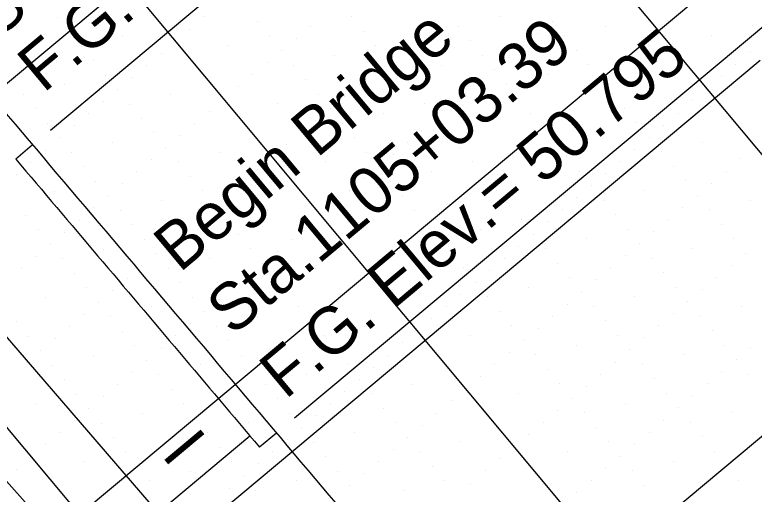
# Model space of a CAD drawing. Extents: x 2042995 to 2043795, y 305365 to 306249.
# Drawn here: x 2043257.9 to 2043297.1, y 305860.14 to 305885.54 of the extents above; entities that cross this region are included whole.
import ezdxf

# ---------------------------------------------------------------- set-up
doc = ezdxf.new("R2010")
doc.units = 0
for name, color, linetype in [('BR_AUTO DIMENSION', 7, 'Continuous'), ('BR_CENTER LINES', 7, 'Continuous'), ('BR_CONCRETE', 7, 'Continuous'), ('BR_EXIST_GROUND_CL', 7, 'Continuous'), ('BR_EXIST_GROUND_LT', 7, 'Continuous'), ('BR_GRID DOTS', 7, 'Continuous'), ('BR_GRID LINES', 7, 'Continuous'), ('BR_TEXT', 7, 'Continuous')]:
    doc.layers.add(name, color=color, linetype=linetype)

msp = doc.modelspace()

# ---------------------------------------------------------------- linework, layer by layer
at = {"layer": 'BR_AUTO DIMENSION'}
for p, q in [((2043259.789, 305879.429), (2043308.056, 305919.741)), ((2043272.73, 305864.18), (2043320.876, 305904.391))]:
    msp.add_line(p, q, dxfattribs=at)
at = {"layer": 'BR_CENTER LINES'}
msp.add_line((2043297.418, 305883.113), (2043258.691, 305850.769), dxfattribs=at)
at = {"layer": 'BR_CONCRETE'}
for p, q in [((2043258.829, 305878.628), (2043257.952, 305877.895)), ((2043271.771, 305863.378), (2043270.876, 305862.631)), ((2043270.361, 305863.212), (2043263.229, 305857.255))]:
    msp.add_line(p, q, dxfattribs=at)
for points in [[(2043139.109, 306017.548), (2043148.199, 306007.16), (2043160.233, 305993.368), (2043172.245, 305979.557), (2043184.234, 305965.727), (2043196.201, 305951.879), (2043208.145, 305938.012), (2043220.067, 305924.126), (2043231.966, 305910.221), (2043243.843, 305896.297), (2043255.698, 305882.355), (2043267.529, 305868.394), (2043279.339, 305854.414), (2043291.126, 305840.415), (2043302.89, 305826.398), (2043314.632, 305812.361), (2043326.352, 305798.306), (2043338.049, 305784.233), (2043349.724, 305770.14), (2043361.376, 305756.029), (2043373.005, 305741.899), (2043384.613, 305727.75), (2043396.197, 305713.582), (2043407.76, 305699.396), (2043419.299, 305685.191), (2043430.817, 305670.967), (2043442.311, 305656.724), (2043453.784, 305642.463), (2043465.234, 305628.182), (2043476.661, 305613.883), (2043488.066, 305599.566), (2043499.448, 305585.229), (2043510.808, 305570.874), (2043522.146, 305556.5), (2043533.461, 305542.107), (2043544.753, 305527.695), (2043547.219, 305524.543)], [(2043257.952, 305877.895), (2043266.634, 305867.646), (2043270.876, 305862.631)]]:
    msp.add_spline(points, degree=3, dxfattribs=at)
at = {"layer": 'BR_EXIST_GROUND_CL'}
msp.add_lwpolyline([(2043190.108, 305945.543), (2043206.09, 305927.482), (2043206.623, 305926.882), (2043222.659, 305908.759), (2043222.667, 305908.751), (2043222.878, 305908.512), (2043223.372, 305907.946), (2043239.214, 305889.588), (2043239.703, 305889.028), (2043255.551, 305870.664), (2043255.733, 305870.455), (2043271.607, 305852.06)], dxfattribs=at)
at = {"layer": 'BR_EXIST_GROUND_LT'}
msp.add_lwpolyline([(2043232.345, 305892.17), (2043232.671, 305891.863), (2043234.146, 305890.054), (2043243.505, 305878.139), (2043246.167, 305875.173), (2043248.035, 305872.016), (2043253.891, 305864.802), (2043257.466, 305860.822), (2043270.561, 305846.11), (2043270.909, 305845.721)], dxfattribs=at)
at = {"layer": 'BR_GRID DOTS'}
for p, q in [((2043260.145, 305885.418), (2043260.145, 305885.418)), ((2043267.956, 305885.426), (2043267.956, 305885.426)), ((2043275.766, 305885.435), (2043275.766, 305885.435)), ((2043283.576, 305885.443), (2043283.576, 305885.443)), ((2043257.969, 305884.903), (2043257.969, 305884.903)), ((2043270.773, 305885.173), (2043270.773, 305885.173)), ((2043273.59, 305884.92), (2043273.59, 305884.92)), ((2043279.991, 305885.055), (2043279.991, 305885.055)), ((2043281.4, 305884.929), (2043281.4, 305884.929)), ((2043286.393, 305885.19), (2043286.393, 305885.19)), ((2043289.21, 305884.937), (2043289.21, 305884.937)), ((2043297.02, 305884.946), (2043297.02, 305884.946)), ((2043267.188, 305884.785), (2043267.188, 305884.785)), ((2043276.407, 305884.667), (2043276.407, 305884.667)), ((2043285.626, 305884.549), (2043285.626, 305884.549)), ((2043263.603, 305884.397), (2043263.603, 305884.397)), ((2043266.42, 305884.144), (2043266.42, 305884.144)), ((2043271.414, 305884.406), (2043271.414, 305884.406)), ((2043272.822, 305884.279), (2043272.822, 305884.279)), ((2043279.224, 305884.414), (2043279.224, 305884.414)), ((2043282.041, 305884.161), (2043282.041, 305884.161)), ((2043287.034, 305884.423), (2043287.034, 305884.423)), ((2043294.844, 305884.432), (2043294.844, 305884.432)), ((2043261.427, 305883.883), (2043261.427, 305883.883)), ((2043269.238, 305883.891), (2043269.238, 305883.891)), ((2043277.048, 305883.9), (2043277.048, 305883.9)), ((2043278.456, 305883.773), (2043278.456, 305883.773)), ((2043284.858, 305883.908), (2043284.858, 305883.908)), ((2043265.653, 305883.503), (2043265.653, 305883.503)), ((2043272.055, 305883.638), (2043272.055, 305883.638)), ((2043274.872, 305883.385), (2043274.872, 305883.385)), ((2043282.682, 305883.394), (2043282.682, 305883.394)), ((2043287.675, 305883.655), (2043287.675, 305883.655)), ((2043296.894, 305883.537), (2043296.894, 305883.537)), ((2043262.068, 305883.115), (2043262.068, 305883.115)), ((2043271.287, 305882.997), (2043271.287, 305882.997)), ((2043277.689, 305883.132), (2043277.689, 305883.132)), ((2043284.091, 305883.267), (2043284.091, 305883.267)), ((2043264.885, 305882.862), (2043264.885, 305882.862)), ((2043272.696, 305882.871), (2043272.696, 305882.871)), ((2043280.506, 305882.879), (2043280.506, 305882.879)), ((2043283.323, 305882.626), (2043283.323, 305882.626)), ((2043288.316, 305882.888), (2043288.316, 305882.888)), ((2043296.126, 305882.896), (2043296.126, 305882.896)), ((2043262.709, 305882.348), (2043262.709, 305882.348)), ((2043264.118, 305882.221), (2043264.118, 305882.221)), ((2043270.52, 305882.356), (2043270.52, 305882.356)), ((2043276.921, 305882.491), (2043276.921, 305882.491)), ((2043278.33, 305882.365), (2043278.33, 305882.365)), ((2043286.14, 305882.373), (2043286.14, 305882.373)), ((2043295.359, 305882.255), (2043295.359, 305882.255)), ((2043260.533, 305881.833), (2043260.533, 305881.833)), ((2043273.337, 305882.103), (2043273.337, 305882.103)), ((2043276.154, 305881.85), (2043276.154, 305881.85)), ((2043282.556, 305881.985), (2043282.556, 305881.985)), ((2043283.964, 305881.859), (2043283.964, 305881.859)), ((2043291.774, 305881.867), (2043291.774, 305881.867)), ((2043263.35, 305881.58), (2043263.35, 305881.58)), ((2043269.752, 305881.715), (2043269.752, 305881.715)), ((2043278.971, 305881.597), (2043278.971, 305881.597)), ((2043289.598, 305881.353), (2043289.598, 305881.353)), ((2043294.591, 305881.614), (2043294.591, 305881.614)), ((2043258.357, 305881.319), (2043258.357, 305881.319)), ((2043266.168, 305881.327), (2043266.168, 305881.327)), ((2043268.985, 305881.074), (2043268.985, 305881.074)), ((2043273.978, 305881.336), (2043273.978, 305881.336)), ((2043275.386, 305881.209), (2043275.386, 305881.209)), ((2043281.788, 305881.344), (2043281.788, 305881.344)), ((2043284.605, 305881.091), (2043284.605, 305881.091)), ((2043293.824, 305880.973), (2043293.824, 305880.973)), ((2043262.583, 305880.939), (2043262.583, 305880.939)), ((2043263.991, 305880.813), (2043263.991, 305880.813)), ((2043271.802, 305880.821), (2043271.802, 305880.821)), ((2043274.619, 305880.568), (2043274.619, 305880.568)), ((2043279.612, 305880.83), (2043279.612, 305880.83)), ((2043281.02, 305880.703), (2043281.02, 305880.703)), ((2043290.239, 305880.585), (2043290.239, 305880.585)), ((2043258.998, 305880.551), (2043258.998, 305880.551)), ((2043261.815, 305880.298), (2043261.815, 305880.298)), ((2043268.217, 305880.433), (2043268.217, 305880.433)), ((2043277.436, 305880.315), (2043277.436, 305880.315)), ((2043285.246, 305880.324), (2043285.246, 305880.324)), ((2043293.056, 305880.332), (2043293.056, 305880.332)), ((2043259.639, 305879.784), (2043259.639, 305879.784)), ((2043264.632, 305880.045), (2043264.632, 305880.045)), ((2043267.45, 305879.792), (2043267.45, 305879.792)), ((2043273.851, 305879.927), (2043273.851, 305879.927)), ((2043275.26, 305879.801), (2043275.26, 305879.801)), ((2043280.253, 305880.062), (2043280.253, 305880.062)), ((2043283.07, 305879.809), (2043283.07, 305879.809)), ((2043290.88, 305879.818), (2043290.88, 305879.818)), ((2043261.048, 305879.657), (2043261.048, 305879.657)), ((2043279.485, 305879.421), (2043279.485, 305879.421)), ((2043292.289, 305879.691), (2043292.289, 305879.691)), ((2043260.28, 305879.016), (2043260.28, 305879.016)), ((2043265.274, 305879.278), (2043265.274, 305879.278)), ((2043266.682, 305879.151), (2043266.682, 305879.151)), ((2043273.084, 305879.286), (2043273.084, 305879.286)), ((2043275.901, 305879.033), (2043275.901, 305879.033)), ((2043280.894, 305879.295), (2043280.894, 305879.295)), ((2043288.704, 305879.303), (2043288.704, 305879.303)), ((2043291.521, 305879.05), (2043291.521, 305879.05)), ((2043263.097, 305878.763), (2043263.097, 305878.763)), ((2043272.316, 305878.645), (2043272.316, 305878.645)), ((2043278.718, 305878.78), (2043278.718, 305878.78)), ((2043286.528, 305878.789), (2043286.528, 305878.789)), ((2043294.338, 305878.797), (2043294.338, 305878.797)), ((2043259.513, 305878.375), (2043259.513, 305878.375)), ((2043260.921, 305878.249), (2043260.921, 305878.249)), ((2043265.915, 305878.51), (2043265.915, 305878.51)), ((2043268.732, 305878.257), (2043268.732, 305878.257)), ((2043276.542, 305878.266), (2043276.542, 305878.266)), ((2043281.535, 305878.527), (2043281.535, 305878.527)), ((2043290.754, 305878.409), (2043290.754, 305878.409)), ((2043292.162, 305878.283), (2043292.162, 305878.283)), ((2043265.147, 305877.869), (2043265.147, 305877.869)), ((2043271.549, 305878.004), (2043271.549, 305878.004)), ((2043277.95, 305878.139), (2043277.95, 305878.139)), ((2043287.169, 305878.021), (2043287.169, 305878.021)), ((2043296.388, 305877.903), (2043296.388, 305877.903)), ((2043258.745, 305877.734), (2043258.745, 305877.734)), ((2043261.562, 305877.481), (2043261.562, 305877.481)), ((2043266.556, 305877.743), (2043266.556, 305877.743)), ((2043274.366, 305877.751), (2043274.366, 305877.751)), ((2043277.183, 305877.498), (2043277.183, 305877.498)), ((2043282.176, 305877.76), (2043282.176, 305877.76)), ((2043289.986, 305877.768), (2043289.986, 305877.768)), ((2043292.803, 305877.515), (2043292.803, 305877.515)), ((2043257.978, 305877.093), (2043257.978, 305877.093)), ((2043264.379, 305877.228), (2043264.379, 305877.228)), ((2043270.781, 305877.363), (2043270.781, 305877.363)), ((2043280, 305877.245), (2043280, 305877.245)), ((2043287.81, 305877.254), (2043287.81, 305877.254)), ((2043289.219, 305877.127), (2043289.219, 305877.127)), ((2043295.62, 305877.262), (2043295.62, 305877.262)), ((2043262.203, 305876.714), (2043262.203, 305876.714)), ((2043267.197, 305876.975), (2043267.197, 305876.975)), ((2043270.014, 305876.722), (2043270.014, 305876.722)), ((2043276.415, 305876.857), (2043276.415, 305876.857)), ((2043277.824, 305876.731), (2043277.824, 305876.731)), ((2043285.634, 305876.739), (2043285.634, 305876.739)), ((2043293.444, 305876.748), (2043293.444, 305876.748)), ((2043263.612, 305876.587), (2043263.612, 305876.587)), ((2043288.451, 305876.486), (2043288.451, 305876.486)), ((2043294.853, 305876.621), (2043294.853, 305876.621)), ((2043260.027, 305876.199), (2043260.027, 305876.199)), ((2043262.844, 305875.946), (2043262.844, 305875.946)), ((2043267.838, 305876.208), (2043267.838, 305876.208)), ((2043269.246, 305876.081), (2043269.246, 305876.081)), ((2043275.648, 305876.216), (2043275.648, 305876.216)), ((2043278.465, 305875.963), (2043278.465, 305875.963)), ((2043283.458, 305876.225), (2043283.458, 305876.225)), ((2043291.268, 305876.233), (2043291.268, 305876.233)), ((2043294.085, 305875.98), (2043294.085, 305875.98)), ((2043265.662, 305875.693), (2043265.662, 305875.693)), ((2043274.88, 305875.575), (2043274.88, 305875.575)), ((2043287.684, 305875.845), (2043287.684, 305875.845)), ((2043289.092, 305875.719), (2043289.092, 305875.719)), ((2043296.903, 305875.727), (2043296.903, 305875.727)), ((2043262.077, 305875.305), (2043262.077, 305875.305)), ((2043263.485, 305875.178), (2043263.485, 305875.178)), ((2043268.479, 305875.44), (2043268.479, 305875.44)), ((2043271.296, 305875.187), (2043271.296, 305875.187)), ((2043279.106, 305875.196), (2043279.106, 305875.196)), ((2043284.099, 305875.457), (2043284.099, 305875.457)), ((2043286.916, 305875.204), (2043286.916, 305875.204)), ((2043293.318, 305875.339), (2043293.318, 305875.339)), ((2043294.726, 305875.213), (2043294.726, 305875.213)), ((2043258.492, 305874.917), (2043258.492, 305874.917)), ((2043267.711, 305874.799), (2043267.711, 305874.799)), ((2043274.113, 305874.934), (2043274.113, 305874.934)), ((2043284.74, 305874.69), (2043284.74, 305874.69)), ((2043289.733, 305874.951), (2043289.733, 305874.951)), ((2043292.55, 305874.698), (2043292.55, 305874.698)), ((2043261.309, 305874.664), (2043261.309, 305874.664)), ((2043264.127, 305874.411), (2043264.127, 305874.411)), ((2043269.12, 305874.673), (2043269.12, 305874.673)), ((2043273.345, 305874.293), (2043273.345, 305874.293)), ((2043276.93, 305874.681), (2043276.93, 305874.681)), ((2043286.149, 305874.563), (2043286.149, 305874.563)), ((2043295.367, 305874.445), (2043295.367, 305874.445)), ((2043259.133, 305874.149), (2043259.133, 305874.149)), ((2043260.542, 305874.023), (2043260.542, 305874.023)), ((2043266.944, 305874.158), (2043266.944, 305874.158)), ((2043269.761, 305873.905), (2043269.761, 305873.905)), ((2043282.564, 305874.175), (2043282.564, 305874.175)), ((2043285.381, 305873.922), (2043285.381, 305873.922)), ((2043290.374, 305874.184), (2043290.374, 305874.184)), ((2043291.783, 305874.057), (2043291.783, 305874.057)), ((2043264.768, 305873.643), (2043264.768, 305873.643)), ((2043266.176, 305873.517), (2043266.176, 305873.517)), ((2043272.578, 305873.652), (2043272.578, 305873.652)), ((2043280.388, 305873.661), (2043280.388, 305873.661)), ((2043288.198, 305873.669), (2043288.198, 305873.669)), ((2043296.008, 305873.678), (2043296.008, 305873.678)), ((2043259.774, 305873.382), (2043259.774, 305873.382)), ((2043262.591, 305873.129), (2043262.591, 305873.129)), ((2043270.402, 305873.137), (2043270.402, 305873.137)), ((2043284.614, 305873.281), (2043284.614, 305873.281)), ((2043286.022, 305873.155), (2043286.022, 305873.155)), ((2043291.015, 305873.416), (2043291.015, 305873.416)), ((2043293.832, 305873.163), (2043293.832, 305873.163)), ((2043259.007, 305872.741), (2043259.007, 305872.741)), ((2043265.409, 305872.876), (2043265.409, 305872.876)), ((2043271.81, 305873.011), (2043271.81, 305873.011)), ((2043281.029, 305872.893), (2043281.029, 305872.893)), ((2043290.248, 305872.775), (2043290.248, 305872.775)), ((2043296.65, 305872.91), (2043296.65, 305872.91)), ((2043260.415, 305872.614), (2043260.415, 305872.614)), ((2043268.226, 305872.623), (2043268.226, 305872.623)), ((2043271.043, 305872.37), (2043271.043, 305872.37)), ((2043283.846, 305872.64), (2043283.846, 305872.64)), ((2043286.663, 305872.387), (2043286.663, 305872.387)), ((2043291.656, 305872.649), (2043291.656, 305872.649)), ((2043258.239, 305872.1), (2043258.239, 305872.1)), ((2043264.641, 305872.235), (2043264.641, 305872.235)), ((2043266.05, 305872.108), (2043266.05, 305872.108)), ((2043273.86, 305872.117), (2043273.86, 305872.117)), ((2043281.67, 305872.126), (2043281.67, 305872.126)), ((2043283.079, 305871.999), (2043283.079, 305871.999)), ((2043289.48, 305872.134), (2043289.48, 305872.134)), ((2043295.882, 305872.269), (2043295.882, 305872.269)), ((2043261.056, 305871.847), (2043261.056, 305871.847)), ((2043263.874, 305871.594), (2043263.874, 305871.594)), ((2043270.275, 305871.729), (2043270.275, 305871.729)), ((2043271.684, 305871.602), (2043271.684, 305871.602)), ((2043279.494, 305871.611), (2043279.494, 305871.611)), ((2043287.304, 305871.62), (2043287.304, 305871.62)), ((2043292.297, 305871.881), (2043292.297, 305871.881)), ((2043295.114, 305871.628), (2043295.114, 305871.628)), ((2043266.691, 305871.341), (2043266.691, 305871.341)), ((2043282.311, 305871.358), (2043282.311, 305871.358)), ((2043288.713, 305871.493), (2043288.713, 305871.493)), ((2043261.697, 305871.079), (2043261.697, 305871.079)), ((2043263.106, 305870.953), (2043263.106, 305870.953)), ((2043269.508, 305871.088), (2043269.508, 305871.088)), ((2043272.325, 305870.835), (2043272.325, 305870.835)), ((2043285.128, 305871.105), (2043285.128, 305871.105)), ((2043287.945, 305870.852), (2043287.945, 305870.852)), ((2043292.938, 305871.114), (2043292.938, 305871.114)), ((2043294.347, 305870.987), (2043294.347, 305870.987)), ((2043259.521, 305870.565), (2043259.521, 305870.565)), ((2043267.332, 305870.573), (2043267.332, 305870.573)), ((2043268.74, 305870.447), (2043268.74, 305870.447)), ((2043281.544, 305870.717), (2043281.544, 305870.717)), ((2043282.952, 305870.59), (2043282.952, 305870.59)), ((2043290.762, 305870.599), (2043290.762, 305870.599)), ((2043262.338, 305870.312), (2043262.338, 305870.312)), ((2043265.156, 305870.059), (2043265.156, 305870.059)), ((2043272.966, 305870.067), (2043272.966, 305870.067)), ((2043280.776, 305870.076), (2043280.776, 305870.076)), ((2043287.178, 305870.211), (2043287.178, 305870.211)), ((2043288.586, 305870.085), (2043288.586, 305870.085)), ((2043293.579, 305870.346), (2043293.579, 305870.346)), ((2043296.397, 305870.093), (2043296.397, 305870.093)), ((2043261.571, 305869.671), (2043261.571, 305869.671)), ((2043267.973, 305869.806), (2043267.973, 305869.806)), ((2043283.593, 305869.823), (2043283.593, 305869.823)), ((2043292.812, 305869.705), (2043292.812, 305869.705)), ((2043257.986, 305869.283), (2043257.986, 305869.283)), ((2043262.98, 305869.544), (2043262.98, 305869.544)), ((2043270.79, 305869.553), (2043270.79, 305869.553)), ((2043280.009, 305869.435), (2043280.009, 305869.435)), ((2043286.41, 305869.57), (2043286.41, 305869.57)), ((2043289.227, 305869.317), (2043289.227, 305869.317)), ((2043294.22, 305869.579), (2043294.22, 305869.579)), ((2043260.803, 305869.03), (2043260.803, 305869.03)), ((2043267.205, 305869.165), (2043267.205, 305869.165)), ((2043268.614, 305869.038), (2043268.614, 305869.038)), ((2043276.424, 305869.047), (2043276.424, 305869.047)), ((2043284.234, 305869.055), (2043284.234, 305869.055)), ((2043285.643, 305868.929), (2043285.643, 305868.929)), ((2043292.044, 305869.064), (2043292.044, 305869.064)), ((2043294.861, 305868.811), (2043294.861, 305868.811)), ((2043258.627, 305868.515), (2043258.627, 305868.515)), ((2043263.621, 305868.777), (2043263.621, 305868.777)), ((2043266.438, 305868.524), (2043266.438, 305868.524)), ((2043274.248, 305868.532), (2043274.248, 305868.532)), ((2043279.241, 305868.794), (2043279.241, 305868.794)), ((2043282.058, 305868.541), (2043282.058, 305868.541)), ((2043289.868, 305868.549), (2043289.868, 305868.549)), ((2043291.277, 305868.423), (2043291.277, 305868.423)), ((2043260.036, 305868.389), (2043260.036, 305868.389)), ((2043269.255, 305868.271), (2043269.255, 305868.271)), ((2043278.473, 305868.153), (2043278.473, 305868.153)), ((2043284.875, 305868.288), (2043284.875, 305868.288)), ((2043287.692, 305868.035), (2043287.692, 305868.035)), ((2043295.503, 305868.044), (2043295.503, 305868.044)), ((2043259.268, 305867.748), (2043259.268, 305867.748)), ((2043264.262, 305868.009), (2043264.262, 305868.009)), ((2043265.67, 305867.883), (2043265.67, 305867.883)), ((2043274.889, 305867.765), (2043274.889, 305867.765)), ((2043284.108, 305867.647), (2043284.108, 305867.647)), ((2043290.509, 305867.782), (2043290.509, 305867.782)), ((2043296.911, 305867.917), (2043296.911, 305867.917)), ((2043262.085, 305867.495), (2043262.085, 305867.495)), ((2043264.903, 305867.242), (2043264.903, 305867.242)), ((2043269.896, 305867.503), (2043269.896, 305867.503)), ((2043277.706, 305867.512), (2043277.706, 305867.512)), ((2043285.516, 305867.52), (2043285.516, 305867.52)), ((2043293.326, 305867.529), (2043293.326, 305867.529)), ((2043296.144, 305867.276), (2043296.144, 305867.276)), ((2043258.501, 305867.107), (2043258.501, 305867.107)), ((2043259.909, 305866.98), (2043259.909, 305866.98)), ((2043267.72, 305866.989), (2043267.72, 305866.989)), ((2043275.53, 305866.997), (2043275.53, 305866.997)), ((2043276.938, 305866.871), (2043276.938, 305866.871)), ((2043283.34, 305867.006), (2043283.34, 305867.006)), ((2043289.742, 305867.141), (2043289.742, 305867.141)), ((2043291.15, 305867.014), (2043291.15, 305867.014)), ((2043264.135, 305866.601), (2043264.135, 305866.601)), ((2043265.544, 305866.474), (2043265.544, 305866.474)), ((2043273.354, 305866.483), (2043273.354, 305866.483)), ((2043286.157, 305866.753), (2043286.157, 305866.753)), ((2043288.974, 305866.5), (2043288.974, 305866.5)), ((2043295.376, 305866.635), (2043295.376, 305866.635)), ((2043296.785, 305866.508), (2043296.785, 305866.508)), ((2043260.55, 305866.213), (2043260.55, 305866.213)), ((2043276.171, 305866.23), (2043276.171, 305866.23)), ((2043282.573, 305866.365), (2043282.573, 305866.365)), ((2043291.791, 305866.247), (2043291.791, 305866.247)), ((2043263.368, 305865.96), (2043263.368, 305865.96)), ((2043266.185, 305865.707), (2043266.185, 305865.707)), ((2043271.178, 305865.968), (2043271.178, 305865.968)), ((2043278.988, 305865.977), (2043278.988, 305865.977)), ((2043281.805, 305865.724), (2043281.805, 305865.724)), ((2043286.798, 305865.985), (2043286.798, 305865.985)), ((2043288.207, 305865.859), (2043288.207, 305865.859)), ((2043294.609, 305865.994), (2043294.609, 305865.994)), ((2043261.191, 305865.445), (2043261.191, 305865.445)), ((2043262.6, 305865.319), (2043262.6, 305865.319)), ((2043275.403, 305865.589), (2043275.403, 305865.589)), ((2043276.812, 305865.462), (2043276.812, 305865.462)), ((2043284.622, 305865.471), (2043284.622, 305865.471)), ((2043292.432, 305865.479), (2043292.432, 305865.479)), ((2043293.841, 305865.353), (2043293.841, 305865.353)), ((2043259.015, 305864.931), (2043259.015, 305864.931)), ((2043266.826, 305864.939), (2043266.826, 305864.939)), ((2043271.819, 305865.201), (2043271.819, 305865.201)), ((2043274.636, 305864.948), (2043274.636, 305864.948)), ((2043281.038, 305865.083), (2043281.038, 305865.083)), ((2043287.439, 305865.218), (2043287.439, 305865.218)), ((2043290.256, 305864.965), (2043290.256, 305864.965)), ((2043261.833, 305864.678), (2043261.833, 305864.678)), ((2043277.453, 305864.695), (2043277.453, 305864.695)), ((2043286.672, 305864.577), (2043286.672, 305864.577)), ((2043293.073, 305864.712), (2043293.073, 305864.712)), ((2043264.65, 305864.425), (2043264.65, 305864.425)), ((2043272.46, 305864.433), (2043272.46, 305864.433)), ((2043273.868, 305864.307), (2043273.868, 305864.307)), ((2043280.27, 305864.442), (2043280.27, 305864.442)), ((2043288.08, 305864.45), (2043288.08, 305864.45)), ((2043295.891, 305864.459), (2043295.891, 305864.459)), ((2043261.065, 305864.037), (2043261.065, 305864.037)), ((2043262.474, 305863.91), (2043262.474, 305863.91)), ((2043270.284, 305863.919), (2043270.284, 305863.919)), ((2043278.094, 305863.927), (2043278.094, 305863.927)), ((2043279.503, 305863.801), (2043279.503, 305863.801)), ((2043285.904, 305863.936), (2043285.904, 305863.936)), ((2043292.306, 305864.071), (2043292.306, 305864.071)), ((2043293.715, 305863.944), (2043293.715, 305863.944)), ((2043260.297, 305863.396), (2043260.297, 305863.396)), ((2043268.108, 305863.404), (2043268.108, 305863.404)), ((2043273.101, 305863.666), (2043273.101, 305863.666)), ((2043275.918, 305863.413), (2043275.918, 305863.413)), ((2043288.721, 305863.683), (2043288.721, 305863.683)), ((2043291.538, 305863.43), (2043291.538, 305863.43)), ((2043263.115, 305863.143), (2043263.115, 305863.143)), ((2043272.333, 305863.025), (2043272.333, 305863.025)), ((2043278.735, 305863.16), (2043278.735, 305863.16)), ((2043285.137, 305863.295), (2043285.137, 305863.295)), ((2043294.356, 305863.177), (2043294.356, 305863.177)), ((2043259.53, 305862.755), (2043259.53, 305862.755)), ((2043268.749, 305862.637), (2043268.749, 305862.637)), ((2043273.742, 305862.898), (2043273.742, 305862.898)), ((2043281.552, 305862.907), (2043281.552, 305862.907)), ((2043284.369, 305862.654), (2043284.369, 305862.654)), ((2043289.362, 305862.915), (2043289.362, 305862.915)), ((2043290.771, 305862.789), (2043290.771, 305862.789)), ((2043263.756, 305862.375), (2043263.756, 305862.375)), ((2043271.566, 305862.384), (2043271.566, 305862.384)), ((2043277.968, 305862.519), (2043277.968, 305862.519)), ((2043279.376, 305862.392), (2043279.376, 305862.392)), ((2043287.186, 305862.401), (2043287.186, 305862.401)), ((2043290.003, 305862.148), (2043290.003, 305862.148)), ((2043294.997, 305862.409), (2043294.997, 305862.409)), ((2043258.762, 305862.114), (2043258.762, 305862.114)), ((2043261.58, 305861.861), (2043261.58, 305861.861)), ((2043269.39, 305861.869), (2043269.39, 305861.869)), ((2043274.383, 305862.131), (2043274.383, 305862.131)), ((2043277.2, 305861.878), (2043277.2, 305861.878)), ((2043283.602, 305862.013), (2043283.602, 305862.013)), ((2043292.82, 305861.895), (2043292.82, 305861.895)), ((2043257.995, 305861.473), (2043257.995, 305861.473)), ((2043270.798, 305861.743), (2043270.798, 305861.743)), ((2043275.024, 305861.363), (2043275.024, 305861.363)), ((2043280.017, 305861.625), (2043280.017, 305861.625)), ((2043282.834, 305861.372), (2043282.834, 305861.372)), ((2043289.236, 305861.507), (2043289.236, 305861.507)), ((2043290.644, 305861.38), (2043290.644, 305861.38)), ((2043267.214, 305861.355), (2043267.214, 305861.355)), ((2043270.031, 305861.102), (2043270.031, 305861.102)), ((2043276.432, 305861.237), (2043276.432, 305861.237)), ((2043265.038, 305860.84), (2043265.038, 305860.84)), ((2043272.848, 305860.849), (2043272.848, 305860.849)), ((2043275.665, 305860.596), (2043275.665, 305860.596)), ((2043280.658, 305860.857), (2043280.658, 305860.857)), ((2043282.067, 305860.731), (2043282.067, 305860.731)), ((2043288.468, 305860.866), (2043288.468, 305860.866)), ((2043291.285, 305860.613), (2043291.285, 305860.613)), ((2043296.279, 305860.874), (2043296.279, 305860.874)), ((2043269.263, 305860.461), (2043269.263, 305860.461)), ((2043270.672, 305860.334), (2043270.672, 305860.334)), ((2043278.482, 305860.343), (2043278.482, 305860.343)), ((2043287.701, 305860.225), (2043287.701, 305860.225))]:
    msp.add_line(p, q, dxfattribs=at)
at = {"layer": 'BR_GRID LINES'}
for p, q in [((2043153.138, 306050.98), (2043584.762, 305534.185)), ((2043137.788, 306038.16), (2043569.411, 305521.364)), ((2043122.438, 306025.339), (2043554.061, 305508.544)), ((2043309.908, 305925.676), (2043156.404, 305797.471)), ((2043322.728, 305910.326), (2043169.224, 305782.12)), ((2043335.549, 305894.975), (2043182.045, 305766.77))]:
    msp.add_line(p, q, dxfattribs=at)

# ---------------------------------------------------------------- texts
at = {"layer": 'BR_TEXT'}
for s, rotation, p in [('Sta. 1104+83.37', 39.8684, (2043257.018, 305884.239)), ('F.G. Elev.= 50.661', 39.8684, (2043259.422, 305881.361)), ('Begin Bridge', 39.8684, (2043266.636, 305871.841)), ('Sta.1105+03.39', 39.8684, (2043269.44, 305868.483)), ('F.G. Elev.= 50.795', 39.8684, (2043272.245, 305865.125)), ('I', 309.8684, (2043265.635, 305862.197))]:
    msp.add_text(s, height=2.5, rotation=rotation, dxfattribs=at).set_placement(p)

doc.saveas('drawing.dxf')
